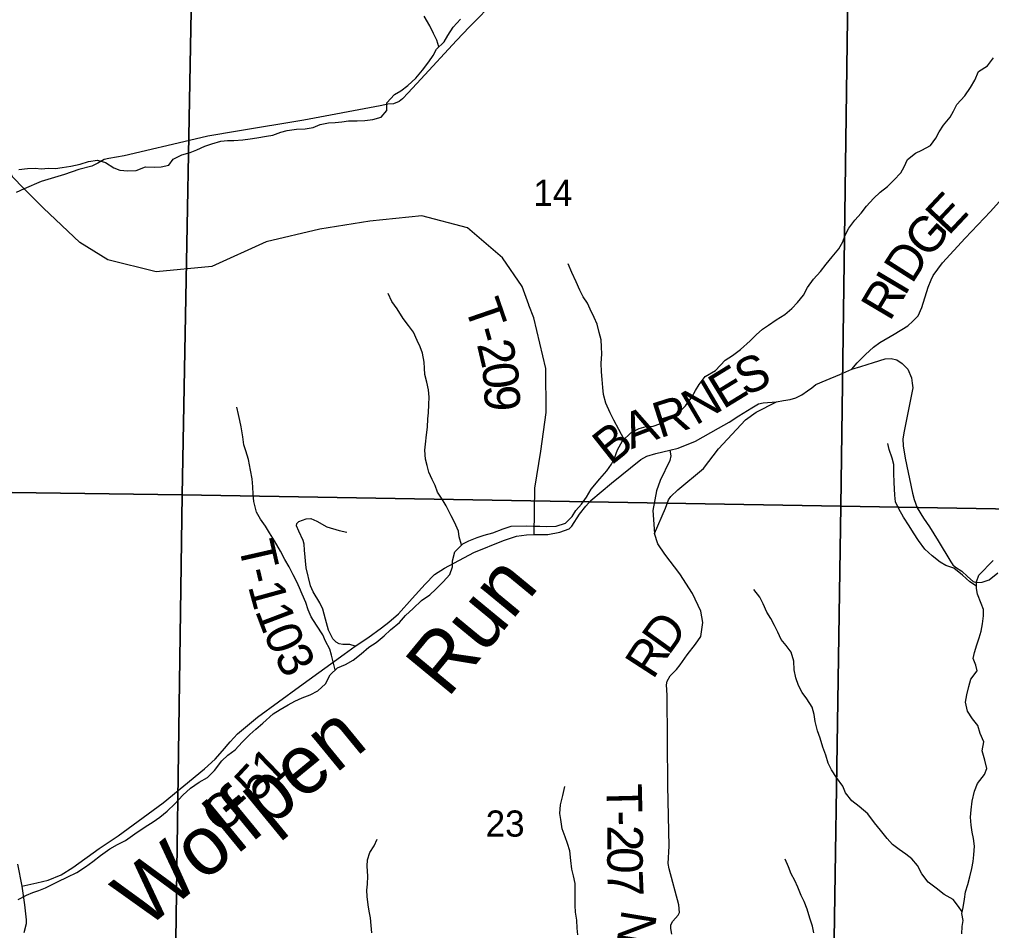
# Model space of a CAD drawing. Extents: x 2043100 to 2470832, y 443715 to 810583.
# Drawn here: x 2278738 to 2286943, y 650684 to 658375 of the extents above; entities that cross this region are included whole.
import ezdxf

# ---------------------------------------------------------------- set-up
doc = ezdxf.new("R2010")
doc.units = 0
for name, color, linetype in [('GM_X_County_Road', 7, 'Continuous'), ('GM_X_County_Road_Text', 7, 'Continuous'), ('GM_X_Minor_River', 7, 'Continuous'), ('GM_X_Minor_River_Text', 7, 'Continuous'), ('GM_X_Section', 7, 'Continuous'), ('GM_X_Section_Text', 7, 'Continuous'), ('GM_X_Township_Road', 7, 'Continuous'), ('GM_X_Township_Road_Text', 7, 'Continuous'), ('GM_X_Township_ROW', 7, 'Continuous')]:
    doc.layers.add(name, color=color, linetype=linetype)

msp = doc.modelspace()

# ---------------------------------------------------------------- linework, layer by layer
at = {"layer": 'GM_X_County_Road'}
for points in [[(2282759.2, 658537.5), (2282537, 658312.9), (2282427, 658196.6), (2282126.8, 657871.7), (2282018.7, 657755.4), (2281970.7, 657705.3), (2281942.7, 657681.2), (2281896.7, 657663.1), (2281846.6, 657659.1), (2281782.5, 657645.1), (2281139.9, 657524.6), (2280579.3, 657430.2), (2280329, 657390), (2280220.9, 657363.9), (2279622.3, 657223.4), (2279492.2, 657201.3), (2279452.2, 657191.3), (2279400.1, 657161.2), (2279350.1, 657135.1), (2279240, 657109), (2279117.8, 657066.9), (2278921.6, 657006.7), (2278779.5, 656944.5)], [(2278410.4, 658413.9), (2278426.4, 658373.8), (2278438.5, 658293.6), (2278440.7, 657916.7), (2278430.8, 657712.2), (2278434.8, 657654.1), (2278446.8, 657593.9), (2278581.2, 657241.1), (2278613.2, 657156.9), (2278635.3, 657118.9), (2278677.4, 657048.7), (2278779.5, 656944.5)], [(2278779.5, 656944.5), (2278709.5, 656914.4)], [(2278758.1, 651058.6), (2278884.3, 651086.7), (2278980.4, 651108.7), (2279090.5, 651154.9), (2279188.5, 651215), (2279410.7, 651375.4), (2279572.8, 651483.7), (2279951.2, 651762.3), (2280299.4, 652049), (2280389.5, 652131.2), (2280451.5, 652201.3), (2280515.6, 652275.5), (2280579.6, 652343.6), (2280747.7, 652484), (2281102, 652744.6), (2281480.3, 653017.2), (2281572.4, 653085.4), (2281678.5, 653155.6), (2281794.6, 653239.8), (2281856.6, 653285.9), (2281936.7, 653356.1), (2282052.7, 653486.3), (2282162.8, 653608.6), (2282242.9, 653688.8), (2282324.9, 653742.9), (2282573.2, 653875.3), (2282823.4, 653977.6), (2282933.5, 654011.7), (2283017.6, 654023.7), (2283081.6, 654027.8), (2283197.8, 654025.8), (2283299.9, 654045.9), (2283378, 654076), (2283400, 654096), (2283466, 654198.2), (2283520, 654266.4), (2283560.1, 654314.5), (2283736.2, 654460.8), (2283982.4, 654659.3), (2284032.4, 654689.4), (2284108.5, 654711.5), (2284226.6, 654737.6), (2284298.7, 654755.6), (2284444.8, 654813.8), (2284639.1, 654923.8), (2284728.5, 654974.9), (2284809.9, 655028), (2284919.1, 655097.4), (2284976.8, 655130.2), (2285014.7, 655138.6), (2285128.6, 655148), (2285188.6, 655156.7), (2285244.5, 655167.4), (2285290.3, 655181.9), (2285342.1, 655206.6), (2285389.7, 655239.2), (2285425.4, 655265.7), (2285459.1, 655292.2), (2285546.7, 655329.3), (2285662.2, 655376.7), (2285763.7, 655422), (2285809.1, 655474.7), (2285880.3, 655547.7), (2285947.6, 655608.6), (2285999.2, 655647.3), (2286120.4, 655718.9), (2286235.6, 655788.4), (2286279.2, 655827), (2286322.6, 655873.6), (2286355.9, 655942.1), (2286409.8, 656115.2), (2286433.1, 656175.6), (2286450.7, 656213.9), (2286529.5, 656321.1), (2286721.1, 656527.8), (2286934.5, 656752.9), (2287007.6, 656833.9)], [(2278722, 651242.9), (2278758.1, 651058.6), (2278780.2, 650900.3), (2278788.3, 650826.1), (2278796.3, 650774.1), (2278796.3, 650740), (2278776.3, 650665.8)]]:
    msp.add_lwpolyline(points, dxfattribs=at)
at = {"layer": 'GM_X_Minor_River'}
for points in [[(2282278.7, 658143.3), (2282261.7, 658200.1), (2282233.1, 658255.9), (2282202.5, 658319.7), (2282155.6, 658403.4)], [(2278732.1, 657108.7), (2278806, 657117.5), (2278872, 657118.1), (2278924, 657114.7), (2278981.9, 657119.2), (2279041.9, 657115.9), (2279099.8, 657124.5), (2279171.7, 657137.2), (2279249.5, 657154), (2279321.3, 657174.8), (2279397.1, 657185.5), (2279465.3, 657166.2), (2279533.7, 657122.8), (2279585.9, 657103.3), (2279653.9, 657098), (2279723.9, 657098.7), (2279803.6, 657129.6), (2279875.6, 657126.3), (2279935.5, 657130.9), (2279999.3, 657145.5), (2280036.8, 657196), (2280108.4, 657230.8), (2280180.2, 657251.5), (2280235.9, 657274.1), (2280303.6, 657304.9), (2280361.4, 657325.5), (2280439.1, 657346.3), (2280493, 657352.9), (2280549, 657353.4), (2280622.9, 657358.2), (2280686.8, 657366.8), (2280740.7, 657375.4), (2280822.6, 657388.2), (2280878.4, 657398.8), (2280944.2, 657423.5), (2280998, 657436.1), (2281075.8, 657448.9), (2281149.8, 657451.6), (2281217.7, 657462.3), (2281277.4, 657489), (2281347.2, 657501.7), (2281403.2, 657504.3), (2281459.1, 657510.8), (2281517, 657517.4), (2281589, 657518.2), (2281654.9, 657522.8), (2281720.8, 657529.5), (2281790.6, 657548.3), (2281838, 657604.8), (2281839.3, 657670.9), (2281902.6, 657739.7), (2281958.2, 657772.3), (2282017.7, 657817), (2282085.1, 657879.8), (2282140.3, 657946.4), (2282193.6, 658017.1), (2282231, 658069.6), (2282258.5, 658123.9), (2282321.8, 658184.7), (2282355.3, 658239.1), (2282398.5, 658309.7), (2282459.8, 658376.4)], [(2284612.4, 655410.4), (2284693.9, 655499), (2284755.6, 655537.4), (2284823.2, 655589.9), (2284906.8, 655660.5), (2284956.4, 655712.9), (2285010.1, 655759.3), (2285061.9, 655793.7), (2285125.5, 655840.2), (2285199.2, 655884.7), (2285258.9, 655935.1), (2285306.5, 655985.5), (2285356.1, 656047.9), (2285389.7, 656112.2), (2285439.3, 656182.6), (2285498.9, 656247.1), (2285548.5, 656307.5), (2285598.1, 656371.9), (2285655.6, 656438.4), (2285687.2, 656498.7), (2285706.9, 656552.9), (2285738.5, 656613.2), (2285790.1, 656681.6), (2285843.7, 656740), (2285887.3, 656798.4), (2285946.9, 656862.9), (2286002.5, 656917.3), (2286066.2, 656963.8), (2286119.8, 657018.2), (2286177.4, 657080.6), (2286205.1, 657130.9), (2286232.7, 657193.2), (2286302.4, 657245.7), (2286356.2, 657272.1), (2286427.9, 657310.6), (2286473.5, 657372.9), (2286501.2, 657425.2), (2286538.8, 657481.5), (2286594.3, 657550), (2286622, 657600.3), (2286651.7, 657656.6), (2286717.2, 657731.1), (2286764.7, 657799.5), (2286802.3, 657861.9), (2286833.9, 657934.2), (2286909.5, 657982.8), (2286959.1, 658051.2)], [(2283842.2, 654830.2), (2283797, 654912.8), (2283756.2, 654992.5), (2283723.6, 655054.2), (2283686.8, 655135.9), (2283668.1, 655207.8), (2283661.4, 655267.9), (2283656.8, 655333.9), (2283650.1, 655399.9), (2283649.3, 655472), (2283654.6, 655548.2), (2283651.9, 655610.2), (2283647.3, 655670.3), (2283632.7, 655732.2), (2283614, 655802.1), (2283589.4, 655857.9), (2283556.7, 655927.7), (2283534.2, 655979.5), (2283497.6, 656033.3), (2283469.1, 656089), (2283438.3, 656160.8), (2283401.5, 656238.6), (2283370.8, 656310.4)], [(2282470.5, 653939.2), (2282448.8, 654006), (2282444.3, 654056), (2282411.5, 654131.8), (2282383, 654183.5), (2282340.2, 654269.2), (2282307.6, 654325), (2282267, 654384.6), (2282246.4, 654440.5), (2282221.9, 654492.3), (2282193.3, 654554.1), (2282178.7, 654610), (2282166.2, 654661.9), (2282159.4, 654738), (2282164.9, 654788.1), (2282174.1, 654868.3), (2282181.4, 654932.5), (2282184.7, 655004.6), (2282190.1, 655054.7), (2282193.4, 655124.8), (2282196.8, 655186.9), (2282190.2, 655247), (2282175.5, 655312.9), (2282158.8, 655378.8), (2282158.3, 655430.9), (2282153.7, 655482.9), (2282139, 655558.9), (2282120.4, 655610.8), (2282095.9, 655664.6), (2282065.2, 655734.4), (2282022.6, 655792), (2281978, 655851.6), (2281927.2, 655933.2), (2281882.6, 655994.9), (2281851.9, 656060.7)], [(2278727.5, 650944.7), (2278797.1, 650981.5), (2278850.9, 651004), (2278902.7, 651022.6), (2278958.4, 651045.2), (2279014.1, 651071.8), (2279065.8, 651098.3), (2279141.4, 651135.1), (2279223, 651174), (2279296.5, 651220.8), (2279358, 651267.5), (2279423.5, 651316.2), (2279500.9, 651373), (2279566.5, 651409.7), (2279634.1, 651444.5), (2279713.5, 651501.3), (2279798.9, 651558.3), (2279866.4, 651601), (2279924, 651641.6), (2279985.4, 651690.3), (2280050.8, 651753), (2280116, 651827.8), (2280181.4, 651886.5), (2280254.8, 651935.3), (2280324.4, 651976.1), (2280385.8, 652034.8), (2280446.9, 652115.5), (2280498.4, 652164), (2280557.9, 652210.7), (2280619.2, 652275.4), (2280682.5, 652340.1), (2280734, 652384.7), (2280791.5, 652433.3), (2280880.7, 652514.3), (2280938.3, 652548.9), (2281005.9, 652589.7), (2281061.5, 652620.3), (2281125.2, 652649), (2281190.9, 652673.7), (2281256.6, 652706.4), (2281321.9, 652765.1), (2281361.1, 652841.6), (2281422.5, 652902.3), (2281490.2, 652931), (2281553.8, 652965.7), (2281621.2, 653018.4), (2281688.6, 653077.2), (2281748.2, 653115.8), (2281817.6, 653170.6), (2281871.1, 653223.2), (2281946.4, 653284), (2281995.8, 653344.6), (2282061.1, 653403.3), (2282132.4, 653470.1), (2282201.9, 653516.9), (2282253.4, 653565.5), (2282314.8, 653626.2), (2282372.1, 653688.8), (2282393.4, 653755.1), (2282394.9, 653805.2), (2282412.1, 653879.5), (2282479.4, 653948.2), (2282531.1, 653974.8), (2282600.8, 654001.5), (2282660.6, 654020.2), (2282734.4, 654040.9), (2282820, 654075.8), (2282887.7, 654098.5), (2283015.7, 654099.8), (2283073.7, 654098.4), (2283129.7, 654097), (2283189.6, 654095.6), (2283267.6, 654096.4), (2283347.3, 654123.2), (2283402.7, 654177.8), (2283434.2, 654230.2), (2283483.6, 654282.8), (2283525, 654341.3), (2283564.3, 654409.8), (2283637.4, 654496.6), (2283696.6, 654565.3), (2283736.1, 654621.8), (2283761.5, 654672.1), (2283786.8, 654740.4), (2283828, 654817), (2283899.3, 654883.8), (2283968.9, 654922.5), (2284028.7, 654937.2), (2284086.6, 654941.7), (2284142.4, 654962.3), (2284218, 654997.2), (2284275.7, 655031.8), (2284358.8, 655112.7), (2284414, 655185.4), (2284445.4, 655243.8), (2284474.9, 655294.1), (2284526.2, 655360.7), (2284612.4, 655410.4)], [(2281404.2, 652884.2), (2281386, 652952), (2281373.4, 653007.9), (2281356.9, 653059.8), (2281320.2, 653127.5), (2281299.7, 653179.4), (2281246.9, 653262.9), (2281200.2, 653332.5), (2281175.6, 653392.4), (2281154.9, 653454.2), (2281124.2, 653522), (2281101.7, 653575.8), (2281079.2, 653627.7), (2281048.6, 653687.4), (2281015.9, 653753.2), (2280979.3, 653814.9), (2280940.6, 653886.6), (2280889.7, 653972.2), (2280849, 654041.8), (2280814.4, 654097.6), (2280773.9, 654155.2), (2280739.3, 654215), (2280716.3, 654304.8), (2280711.7, 654366.9), (2280709.1, 654428.9), (2280702.4, 654496.9), (2280689.6, 654570.9), (2280670.7, 654660.8), (2280648, 654732.7), (2280633.4, 654784.6), (2280622.7, 654852.6), (2280609.9, 654936.6), (2280597.3, 654988.5), (2280586.8, 655040.5), (2280572.2, 655102.4)], [(2286816.1, 653590.3), (2286761.2, 653626.2), (2286697, 653683.9), (2286624.7, 653741.6), (2286558.6, 653765.2), (2286508.5, 653792.9), (2286442.2, 653846.6), (2286379.9, 653904.4), (2286327.5, 653976.2), (2286285.2, 654042), (2286246.9, 654099.9), (2286200.5, 654173.7), (2286160.1, 654243.6), (2286133.8, 654303.5), (2286127.5, 654357.6), (2286123.1, 654413.7), (2286120.8, 654465.7), (2286118.4, 654545.8), (2286117.9, 654618), (2286103.6, 654672), (2286079.2, 654743.9), (2286066.9, 654794)], [(2286692.7, 650655.2), (2286694.3, 650717.3), (2286704, 650767.5), (2286691.6, 650827.5), (2286703.3, 650879.6), (2286714.9, 650947.8), (2286724.6, 651010), (2286742.2, 651072.2), (2286759.8, 651138.4), (2286777.4, 651208.6), (2286787, 651266.7), (2286794.7, 651322.8), (2286798.2, 651397), (2286789.9, 651461), (2286779.6, 651515), (2286771.2, 651573.1), (2286766.8, 651641.2), (2286772.5, 651703.3), (2286780, 651775.4), (2286799.5, 651859.7), (2286825.1, 651923.9), (2286884.6, 652000.4), (2286904.3, 652050.6), (2286887.9, 652122.6), (2286863.5, 652200.6), (2286877, 652276.8), (2286846.7, 652346.7), (2286826.3, 652414.7), (2286782, 652470.5), (2286741.6, 652534.4), (2286723.2, 652612.4), (2286734.8, 652674.5), (2286750.4, 652744.7), (2286768, 652804.9), (2286821.6, 652875.4), (2286811.3, 652925.4), (2286789, 652979.3), (2286798.7, 653031.5), (2286818.3, 653095.7), (2286837.9, 653155.9), (2286855.6, 653212.1), (2286867.2, 653272.2), (2286874.8, 653340.4), (2286874.5, 653392.5), (2286856.2, 653444.5), (2286823.8, 653522.4), (2286815.5, 653572.4), (2286817.2, 653626.5), (2286834.9, 653682.7), (2286958, 653807.6)], [(2286695.1, 650842.9), (2286663.3, 650887.4), (2286619, 650947.2), (2286544.8, 650986.9), (2286476.6, 651040.5), (2286408.3, 651092.2), (2286356, 651162), (2286319.6, 651233.9), (2286271.3, 651289.7), (2286221.1, 651329.5), (2286164.9, 651367.2), (2286108.7, 651408.9), (2286062.4, 651460.7), (2286006.1, 651532.5), (2285955.7, 651594.3), (2285899.3, 651668.1), (2285825.1, 651729.7), (2285762.8, 651779.4), (2285710.5, 651845.2), (2285688.1, 651903.2), (2285635.8, 651977), (2285591.4, 652040.8), (2285565.1, 652096.7), (2285544.7, 652164.7), (2285518.3, 652232.7), (2285495.9, 652308.6), (2285473.6, 652370.6), (2285455.1, 652448.6), (2285446.8, 652508.7), (2285428.5, 652568.6), (2285384.1, 652640.5), (2285343.8, 652692.3), (2285313.5, 652752.2), (2285291.1, 652816.2), (2285278.7, 652884.2), (2285274.3, 652958.3), (2285251.9, 653034.3), (2285209.6, 653090.2), (2285167.3, 653142), (2285139, 653201.9), (2285110.7, 653259.8), (2285080.3, 653317.7), (2285046.1, 653371.6), (2285015.7, 653441.5), (2284987.4, 653497.5), (2284937, 653561.3)], [(2283450.9, 650648.2), (2283446.4, 650704.2), (2283443.7, 650770.3), (2283433, 650840.2), (2283428.4, 650896.2), (2283427.8, 650954.3), (2283429.2, 651018.4), (2283428.5, 651080.4), (2283415.9, 651144.4), (2283401.3, 651202.3), (2283392.5, 651276.3), (2283383.7, 651356.3), (2283365.1, 651418.2), (2283344.5, 651476.1), (2283319.8, 651543.9), (2283309, 651619.9), (2283298.5, 651671.8), (2283303.7, 651743.9), (2283324.9, 651824.3), (2283342.1, 651900.5)], [(2281713.4, 650664.6), (2281706.7, 650726.6), (2281700.1, 650790.6), (2281689.5, 650846.6), (2281681, 650900.6), (2281674.2, 650970.6), (2281671.7, 651024.6), (2281675.2, 651074.7), (2281678.5, 651142.8), (2281673.6, 651226.9), (2281677.1, 651281), (2281696.4, 651343.2), (2281731.8, 651397.6), (2281757.2, 651456)], [(2285443.6, 650665.8), (2285433.3, 650719.9), (2285410.9, 650789.8), (2285388.4, 650863.8), (2285362.1, 650927.8), (2285335.8, 650979.7), (2285307.4, 651049.6), (2285283.1, 651105.6), (2285252.8, 651163.5), (2285228.5, 651221.4), (2285200.1, 651285.3)]]:
    msp.add_lwpolyline(points, dxfattribs=at)
at = {"layer": 'GM_X_Section'}
for points in [[(2280210, 659660.1), (2280112.2, 654362.7), (2274773.1, 654433.9), (2274869, 659715.3)], [(2280210, 659660.1), (2285743.7, 659616.6), (2285670, 654267.2), (2280112.2, 654362.7)], [(2285743.7, 659616.6), (2291093.6, 659500.9), (2291064.4, 655638.8), (2291059.6, 654174.1), (2285670, 654267.2)], [(2280112.2, 654362.7), (2280037, 649021.6), (2274697.8, 649098.8), (2274773.1, 654433.9)], [(2280112.2, 654362.7), (2285670, 654267.2), (2285589.7, 648963.8), (2280037, 649021.6)], [(2285670, 654267.2), (2291059.6, 654174.1), (2291034.9, 650276), (2291005.1, 648893), (2285589.7, 648963.8)]]:
    msp.add_lwpolyline(points, close=True, dxfattribs=at)
at = {"layer": 'GM_X_Township_Road'}
for points in [[(2283081.6, 654027.8), (2283089.5, 654418.5), (2283139.4, 654729.2), (2283185.3, 655055.9), (2283181.1, 655428.6), (2283078.8, 655855.5), (2283038.6, 655963.8)], [(2285763.7, 655422), (2285839, 655445.2), (2285946.9, 655480), (2286044.9, 655510.7), (2286094.9, 655513.1), (2286145.1, 655501.4), (2286189.4, 655471.6), (2286235.8, 655423.8), (2286266.4, 655349.8), (2286274.7, 655303.8), (2286279, 655263.7), (2286259.6, 655167.3), (2286205.4, 654898.3), (2286193.8, 654834), (2286198.3, 654775.9), (2286213, 654671.8), (2286275.2, 654375.4), (2286291.6, 654321.4), (2286316.1, 654253.4), (2286368.8, 654165.5), (2286419.4, 654091.7), (2286492.4, 653973.9), (2286599.8, 653796.2), (2286616, 653770.2), (2286640.2, 653750.4), (2286692.5, 653718.6), (2286740.9, 653672.8), (2286787.2, 653631.1), (2286817.4, 653621.2), (2286863.4, 653623.5), (2286923.4, 653644), (2286997.1, 653702.6)], [(2284244.4, 650653.7), (2284236.3, 650701.8), (2284236.3, 650731.9), (2284252.3, 650763.9), (2284298.4, 650814), (2284310.4, 650836.1), (2284304.3, 650902.2), (2284222.1, 651204.7), (2284214.1, 651248.8), (2284222, 651395.1), (2284211.8, 651906.1), (2284205.5, 652669.5), (2284199.4, 652757.7), (2284205.4, 652787.7), (2284231.4, 652833.8), (2284283.5, 652888), (2284315.5, 652928), (2284373.5, 653012.2), (2284445.6, 653102.4), (2284489.6, 653164.6), (2284507.6, 653284.8), (2284489.5, 653381), (2284419.3, 653529.2), (2284313.2, 653695.5), (2284186.9, 653859.8), (2284126.8, 653948), (2284098.8, 654034.1), (2284190.8, 654248.6), (2284216.8, 654320.7), (2284236.8, 654346.8), (2284294.8, 654402.9), (2284513, 654583.4), (2284639.1, 654749.7), (2284866.3, 654994.6), (2284955.6, 655059.8), (2285128.6, 655148)], [(2284226.6, 654737.6), (2284236.6, 654691.5), (2284228.6, 654651.4), (2284146.6, 654483), (2284114.6, 654396.9), (2284084.7, 654230.5), (2284098.8, 654034.1)], [(2281572.4, 653085.4), (2281528.3, 653099.4), (2281468.3, 653099.4), (2281436.2, 653103.4), (2281410.2, 653119.4), (2281384.1, 653145.5), (2281346.1, 653219.6), (2281322, 653311.8), (2281299.9, 653397.9), (2281273.9, 653450), (2281217.8, 653542.2), (2281195.7, 653592.3), (2281159.6, 653746.6), (2281145.5, 653894.8), (2281141.5, 653944.9), (2281133.5, 653977), (2281097.4, 654055.2), (2281077.4, 654099.2), (2281079.4, 654119.3), (2281097.4, 654137.3), (2281157.5, 654159.4), (2281197.5, 654161.4), (2281247.6, 654139.4), (2281331.7, 654091.3), (2281435.8, 654061.3), (2281501.9, 654045.3)]]:
    msp.add_lwpolyline(points, dxfattribs=at)
at = {"layer": 'GM_X_Township_ROW'}
msp.add_lwpolyline([(2283038.6, 655963.8), (2283038.3, 655964.7), (2282980.6, 656120), (2282816.3, 656362.5), (2282519.9, 656614.9), (2282133.4, 656717), (2281696.9, 656670.8), (2281272.5, 656604.5), (2280820, 656496.1), (2280361.3, 656287.8), (2279893.2, 656245.2), (2279484.6, 656345.4), (2279248.3, 656491.6), (2278941.8, 656780.2), (2278779.5, 656944.5)], dxfattribs=at)

# ---------------------------------------------------------------- texts
at = {"layer": 'GM_X_County_Road_Text'}
for s, rotation, p in [('E', 46.82162, (2286579.6, 656542.6)), ('G', 48.40971, (2286405.8, 656346.8)), ('D', 57.46482, (2286271.4, 656134.2)), ('R', 59.36288, (2286084.3, 655818.5)), ('I', 59.28391, (2286209.8, 656030.4)), ('S', 23.70583, (2284859.7, 655192.3)), ('E', 31.48787, (2284677.9, 655080)), ('N', 30.43899, (2284445.2, 654943.2)), ('R', 17.74006, (2284144.3, 654838.6)), ('A', 21.12225, (2283902.5, 654745)), ('B', 38.40318, (2283730.1, 654603.7)), ('1', 44.01376, (2280869.3, 651886.5)), ('5', 47.16468, (2280746.7, 651754.1)), ('C', 39.5857, (2280433, 651485.8)), ('-', 41.45821, (2280631, 651649.8))]:
    msp.add_text(s, height=300, rotation=rotation, dxfattribs=at).set_placement(p)
at = {"layer": 'GM_X_Minor_River_Text'}
for s, rotation, p in [('Run', 50.49758, (2282351.3, 652637.9)), ('Wolfpen', 39.35597, (2279798.8, 650685.5))]:
    msp.add_text(s, height=499.96, rotation=rotation, dxfattribs=at).set_placement(p)
at = {"layer": 'GM_X_Section_Text'}
for s, p in [('14', (2283076.2, 656800.6)), ('23', (2282673.6, 651476.6))]:
    msp.add_text(s, height=220.83, rotation=0.00001, dxfattribs=at).set_placement(p)
at = {"layer": 'GM_X_Township_Road_Text'}
for s, rotation, p in [('T', 288.99739, (2282492.8, 655956.5)), ('-', 286.11159, (2282564.7, 655748.1)), ('2', 283.29029, (2282597.9, 655633.5)), ('0', 276.91202, (2282638.8, 655462.4)), ('9', 271.40518, (2282660.5, 655286.5)), ('T', 282.82631, (2280583.9, 653942.8)), ('-', 283.42532, (2280634.5, 653720.7)), ('1', 285.40375, (2280665.9, 653589.9)), ('1', 290.7617, (2280724.5, 653382.7)), ('D', 54.3141, (2284217.4, 652998.8)), ('0', 292.44796, (2280793.5, 653201)), ('R', 57.05254, (2284085.5, 652795.2)), ('3', 299.30938, (2280881.2, 652994.9)), ('T', 271.39729, (2283690.9, 651919.5)), ('-', 271.28033, (2283696.3, 651695.3)), ('2', 270.69737, (2283699.1, 651573)), ('0', 268.95392, (2283701.3, 651390.6)), ('7', 272.53486, (2283698.2, 651185.4)), ('N', 80.55145, (2284073.2, 650534.1))]:
    msp.add_text(s, height=300, rotation=rotation, dxfattribs=at).set_placement(p)

doc.saveas('drawing.dxf')
